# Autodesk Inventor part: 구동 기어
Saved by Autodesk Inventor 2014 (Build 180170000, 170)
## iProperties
Created: 2026-04
Part Number: 구동 기어
Material: 강철, 합금
Document SubType Name: Modeling
Designer: dg
Density: 7.85 g/cm^3
Appearance: 반연마
Author: jhkim
Creation Date: 2026-03-27
Sending System: Autodesk Inventor 2026
Preprocessor: ST-DEVELOPER v20.1
Author: dg
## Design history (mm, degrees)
node "구동 기어1"
node "솔리드1"
node "기준1"
